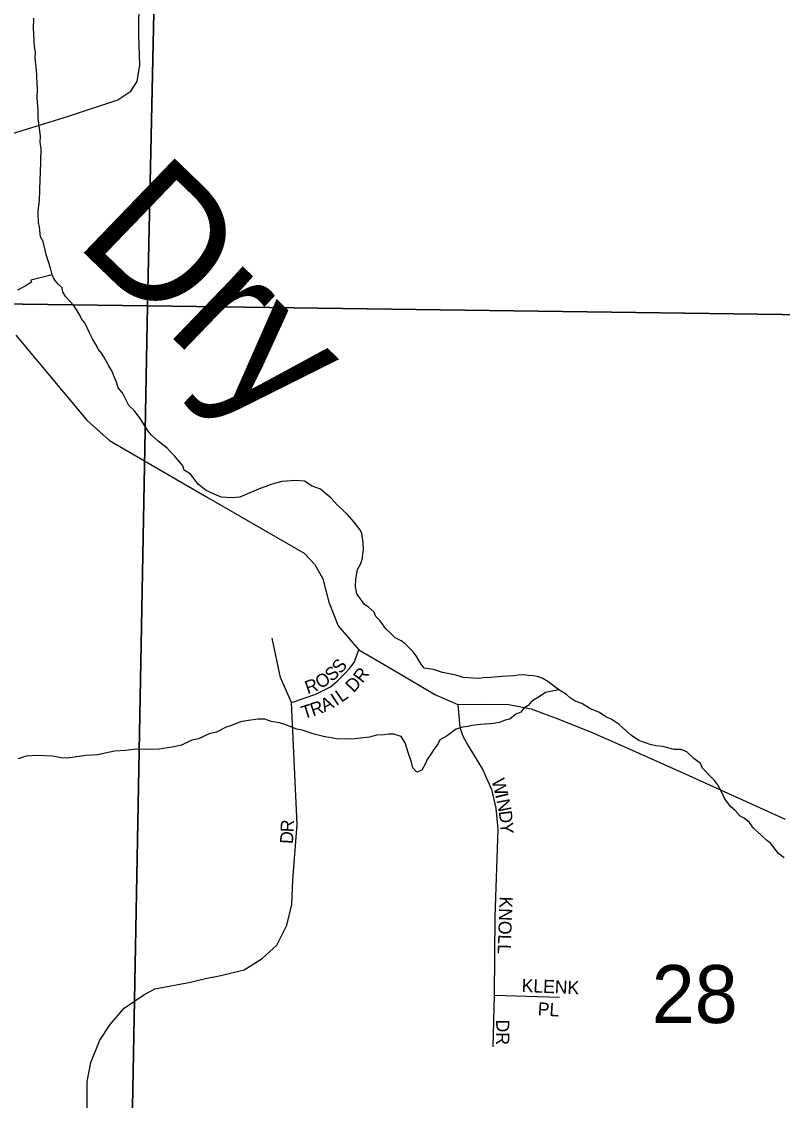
# Model space of a CAD drawing. Extents: x 0 to 34, y -2.3 to 22.
# Drawn here: x 4.226 to 4.776, y 15.821 to 16.601 of the extents above; entities that cross this region are included whole.
import ezdxf

# ---------------------------------------------------------------- set-up
doc = ezdxf.new("R2010")
doc.units = 0
for name, color, linetype in [('GM_X_County_Road', 7, 'Continuous'), ('GM_X_Minor_River', 7, 'Continuous'), ('GM_X_Minor_River_Text', 7, 'Continuous'), ('GM_X_Section', 7, 'Continuous'), ('GM_X_Section_Text', 7, 'Continuous'), ('GM_X_Township_Subdivision', 7, 'Continuous'), ('GM_X_Township_Subdivision_Text', 7, 'Continuous')]:
    doc.layers.add(name, color=color, linetype=linetype)

msp = doc.modelspace()

# ---------------------------------------------------------------- linework, layer by layer
at = {"layer": 'GM_X_County_Road'}
for p, q in [((4.31059, 16.60001), (4.31135, 16.62534)), ((4.31059, 16.59046), (4.31059, 16.60001)), ((4.31148, 16.56919), (4.31059, 16.59046)), ((4.30944, 16.55735), (4.31148, 16.56919)), ((4.30486, 16.55022), (4.30944, 16.55735)), ((4.29544, 16.54411), (4.30486, 16.55022)), ((4.25979, 16.53214), (4.29544, 16.54411)), ((4.17143, 16.50489), (4.25979, 16.53214)), ((4.22166, 16.37393), (4.27308, 16.31263)), ((4.27308, 16.31263), (4.28947, 16.29794)), ((4.28947, 16.29794), (4.35956, 16.25711)), ((4.35956, 16.25711), (4.43018, 16.21663)), ((4.43018, 16.21663), (4.43794, 16.2083)), ((4.43794, 16.2083), (4.44354, 16.19792)), ((4.44354, 16.19792), (4.44787, 16.18103)), ((4.44787, 16.18103), (4.45474, 16.16413)), ((4.45474, 16.16413), (4.46956, 16.14679)), ((4.46956, 16.14679), (4.48745, 16.13624)), ((4.48745, 16.13624), (4.50685, 16.12491)), ((4.50685, 16.12491), (4.52456, 16.11438)), ((4.52456, 16.11438), (4.54123, 16.1073)), ((4.54123, 16.1073), (4.56234, 16.10753)), ((4.56234, 16.10753), (4.57798, 16.10719)), ((4.57798, 16.10719), (4.59418, 16.10399)), ((4.59418, 16.10399), (4.61415, 16.09658)), ((4.61415, 16.09658), (4.63868, 16.08665)), ((4.63868, 16.08665), (4.65865, 16.07809)), ((4.65865, 16.07809), (4.70556, 16.05709)), ((4.70556, 16.05709), (4.77775, 16.02433))]:
    msp.add_line(p, q, dxfattribs=at)
at = {"layer": 'GM_X_Minor_River'}
for p, q in [((4.23456, 16.59498), (4.23479, 16.60295)), ((4.23486, 16.59231), (4.23456, 16.59498)), ((4.23507, 16.58623), (4.23486, 16.59231)), ((4.23535, 16.5828), (4.23507, 16.58623)), ((4.23597, 16.57822), (4.23535, 16.5828)), ((4.23586, 16.57442), (4.23597, 16.57822)), ((4.23674, 16.56528), (4.23586, 16.57442)), ((4.23702, 16.56185), (4.23674, 16.56528)), ((4.2372, 16.55501), (4.23702, 16.56185)), ((4.23749, 16.55196), (4.2372, 16.55501)), ((4.2373, 16.54551), (4.23749, 16.55196)), ((4.2378, 16.53638), (4.2373, 16.54551)), ((4.23801, 16.53067), (4.2378, 16.53638)), ((4.23862, 16.52534), (4.23801, 16.53067)), ((4.23954, 16.51771), (4.23862, 16.52534)), ((4.23941, 16.51354), (4.23954, 16.51771)), ((4.24003, 16.50858), (4.23941, 16.51354)), ((4.23952, 16.49112), (4.24003, 16.50858)), ((4.23895, 16.47139), (4.23939, 16.48657)), ((4.23939, 16.48657), (4.23952, 16.49112)), ((4.23797, 16.46382), (4.23895, 16.47139)), ((4.23789, 16.46116), (4.23797, 16.46382)), ((4.2381, 16.45546), (4.23789, 16.46116)), ((4.23876, 16.45202), (4.2381, 16.45546)), ((4.23971, 16.44515), (4.23876, 16.45202)), ((4.2415, 16.44168), (4.23971, 16.44515)), ((4.24218, 16.43862), (4.2415, 16.44168)), ((4.24386, 16.43135), (4.24218, 16.43862)), ((4.24598, 16.42559), (4.24386, 16.43135)), ((4.247, 16.42138), (4.24598, 16.42559)), ((4.24803, 16.41755), (4.23255, 16.41364)), ((4.24803, 16.41755), (4.247, 16.42138)), ((4.24946, 16.41447), (4.24803, 16.41755)), ((4.25201, 16.41098), (4.24946, 16.41447)), ((4.2284, 16.4094), (4.223, 16.40653)), ((4.23305, 16.4123), (4.2284, 16.4094)), ((4.23255, 16.41364), (4.23305, 16.4123)), ((4.25536, 16.40822), (4.25201, 16.41098)), ((4.25565, 16.40517), (4.25536, 16.40822)), ((4.25783, 16.40169), (4.25565, 16.40517)), ((4.26373, 16.39543), (4.25783, 16.40169)), ((4.26809, 16.38846), (4.26373, 16.39543)), ((4.26915, 16.38577), (4.26809, 16.38846)), ((4.27173, 16.38304), (4.26915, 16.38577)), ((4.27494, 16.37572), (4.27173, 16.38304)), ((4.27709, 16.37148), (4.27494, 16.37572)), ((4.27963, 16.36723), (4.27709, 16.37148)), ((4.28143, 16.36375), (4.27963, 16.36723)), ((4.28363, 16.36103), (4.28143, 16.36375)), ((4.28545, 16.35832), (4.28363, 16.36103)), ((4.28907, 16.35175), (4.28545, 16.35832)), ((4.29124, 16.34826), (4.28907, 16.35175)), ((4.29479, 16.33942), (4.29124, 16.34826)), ((4.29583, 16.33597), (4.29479, 16.33942)), ((4.29877, 16.33246), (4.29583, 16.33597)), ((4.30344, 16.32321), (4.29877, 16.33246)), ((4.30751, 16.31929), (4.30344, 16.32321)), ((4.31153, 16.31385), (4.30751, 16.31929)), ((4.31335, 16.31114), (4.31153, 16.31385)), ((4.31734, 16.30456), (4.31335, 16.31114)), ((4.31992, 16.30182), (4.31734, 16.30456)), ((4.32474, 16.2975), (4.31992, 16.30182)), ((4.33105, 16.29237), (4.32474, 16.2975)), ((4.334, 16.28925), (4.33105, 16.29237)), ((4.33658, 16.28651), (4.334, 16.28925)), ((4.34246, 16.2795), (4.33658, 16.28651)), ((4.34351, 16.27642), (4.34246, 16.2795)), ((4.34799, 16.27363), (4.34351, 16.27642)), ((4.35386, 16.26624), (4.34799, 16.27363)), ((4.35943, 16.26189), (4.35386, 16.26624)), ((4.40861, 16.26688), (4.40554, 16.26583)), ((4.41397, 16.26824), (4.40861, 16.26688)), ((4.42083, 16.2688), (4.41397, 16.26824)), ((4.42388, 16.26909), (4.42083, 16.2688)), ((4.43033, 16.26851), (4.42388, 16.26909)), ((4.43592, 16.26493), (4.43033, 16.26851)), ((4.36731, 16.25824), (4.35943, 16.26189)), ((4.37032, 16.25701), (4.36731, 16.25824)), ((4.39093, 16.26019), (4.38362, 16.25699)), ((4.39709, 16.26267), (4.39093, 16.26019)), ((4.40554, 16.26583), (4.39709, 16.26267)), ((4.44194, 16.26285), (4.43592, 16.26493)), ((4.44973, 16.25616), (4.44194, 16.26285)), ((4.3779, 16.2564), (4.37032, 16.25701)), ((4.38362, 16.25699), (4.3779, 16.2564)), ((4.45415, 16.25109), (4.44973, 16.25616)), ((4.46155, 16.24441), (4.45415, 16.25109)), ((4.46634, 16.23895), (4.46155, 16.24441)), ((4.47074, 16.2335), (4.46634, 16.23895)), ((4.4718, 16.2308), (4.47074, 16.2335)), ((4.47275, 16.22432), (4.4718, 16.2308)), ((4.47297, 16.21861), (4.47275, 16.22432)), ((4.47117, 16.20917), (4.47242, 16.21293)), ((4.47242, 16.21293), (4.47251, 16.21597)), ((4.47251, 16.21597), (4.47297, 16.21861)), ((4.46788, 16.20053), (4.46876, 16.20468)), ((4.46876, 16.20468), (4.47117, 16.20917)), ((4.46726, 16.19219), (4.46741, 16.19751)), ((4.46741, 16.19751), (4.46788, 16.20053)), ((4.46825, 16.18722), (4.46726, 16.19219)), ((4.47373, 16.17946), (4.46825, 16.18722)), ((4.47635, 16.17787), (4.47373, 16.17946)), ((4.48079, 16.17393), (4.47635, 16.17787)), ((4.48184, 16.17086), (4.48079, 16.17393)), ((4.48517, 16.16773), (4.48184, 16.17086)), ((4.48918, 16.16191), (4.48517, 16.16773)), ((4.49251, 16.15877), (4.48918, 16.16191)), ((4.49583, 16.15525), (4.49251, 16.15877)), ((4.50034, 16.15322), (4.49583, 16.15525)), ((4.50294, 16.15124), (4.50034, 16.15322)), ((4.50885, 16.14536), (4.50294, 16.15124)), ((4.51104, 16.14226), (4.50885, 16.14536)), ((4.51467, 16.13645), (4.51104, 16.14226)), ((4.51686, 16.13335), (4.51467, 16.13645)), ((4.52368, 16.13239), (4.51686, 16.13335)), ((4.53008, 16.13029), (4.52368, 16.13239)), ((4.53726, 16.12894), (4.53008, 16.13029)), ((4.54066, 16.12808), (4.53726, 16.12894)), ((4.54518, 16.1268), (4.54066, 16.12808)), ((4.55239, 16.12621), (4.54518, 16.1268)), ((4.55694, 16.12607), (4.55239, 16.12621)), ((4.55961, 16.12637), (4.55694, 16.12607)), ((4.56494, 16.12659), (4.55961, 16.12637)), ((4.57295, 16.12749), (4.56494, 16.12659)), ((4.57714, 16.12775), (4.57295, 16.12749)), ((4.58208, 16.12798), (4.57714, 16.12775)), ((4.58475, 16.12828), (4.58208, 16.12798)), ((4.58894, 16.12853), (4.58475, 16.12828)), ((4.59197, 16.12806), (4.58894, 16.12853)), ((4.59577, 16.12795), (4.59197, 16.12806)), ((4.5988, 16.12748), (4.59577, 16.12795)), ((4.60218, 16.12624), (4.5988, 16.12748)), ((4.60629, 16.12384), (4.60218, 16.12624)), ((4.6141, 16.11791), (4.60454, 16.11591)), ((4.61038, 16.12068), (4.60629, 16.12384)), ((4.6141, 16.11791), (4.61038, 16.12068)), ((4.61672, 16.11631), (4.6141, 16.11791)), ((4.60144, 16.11373), (4.59447, 16.10938)), ((4.60454, 16.11591), (4.60144, 16.11373)), ((4.6197, 16.11432), (4.61672, 16.11631)), ((4.62229, 16.11196), (4.6197, 16.11432)), ((4.62602, 16.10957), (4.62229, 16.11196)), ((4.58901, 16.1046), (4.58664, 16.10163)), ((4.5921, 16.10641), (4.58901, 16.1046)), ((4.59447, 16.10938), (4.5921, 16.10641)), ((4.63092, 16.10791), (4.62602, 16.10957)), ((4.63651, 16.10432), (4.63092, 16.10791)), ((4.64365, 16.10145), (4.63651, 16.10432)), ((4.38423, 16.09476), (4.37768, 16.09192)), ((4.38996, 16.09573), (4.38423, 16.09476)), ((4.39683, 16.09667), (4.38996, 16.09573)), ((4.40176, 16.09652), (4.39683, 16.09667)), ((4.40628, 16.09486), (4.40176, 16.09652)), ((4.41233, 16.09392), (4.40628, 16.09486)), ((4.57545, 16.09589), (4.57122, 16.09412)), ((4.57889, 16.09655), (4.57545, 16.09589)), ((4.58318, 16.10022), (4.57889, 16.09655)), ((4.58664, 16.10163), (4.58318, 16.10022)), ((4.64812, 16.09828), (4.64365, 16.10145)), ((4.65262, 16.09624), (4.64812, 16.09828)), ((4.65784, 16.09267), (4.65262, 16.09624)), ((4.36691, 16.08731), (4.36155, 16.08595)), ((4.37385, 16.0909), (4.36691, 16.08731)), ((4.37768, 16.09192), (4.37385, 16.0909)), ((4.4161, 16.09267), (4.41233, 16.09392)), ((4.42474, 16.08937), (4.4161, 16.09267)), ((4.42966, 16.08847), (4.42474, 16.08937)), ((4.4353, 16.0864), (4.42966, 16.08847)), ((4.53991, 16.08935), (4.53292, 16.08424)), ((4.54451, 16.09073), (4.53991, 16.08935)), ((4.54833, 16.09138), (4.54451, 16.09073)), ((4.55139, 16.09205), (4.54833, 16.09138)), ((4.55749, 16.09263), (4.55139, 16.09205)), ((4.5613, 16.09289), (4.55749, 16.09263)), ((4.56702, 16.09348), (4.5613, 16.09289)), ((4.57122, 16.09412), (4.56702, 16.09348)), ((4.66043, 16.09031), (4.65784, 16.09267)), ((4.66674, 16.0848), (4.66043, 16.09031)), ((4.34887, 16.08138), (4.34154, 16.0778)), ((4.35384, 16.08238), (4.34887, 16.08138)), ((4.36155, 16.08595), (4.35384, 16.08238)), ((4.43832, 16.08555), (4.4353, 16.0864)), ((4.44511, 16.08383), (4.43832, 16.08555)), ((4.44814, 16.08336), (4.44511, 16.08383)), ((4.45343, 16.08244), (4.44814, 16.08336)), ((4.46178, 16.08219), (4.45343, 16.08244)), ((4.46711, 16.08241), (4.46178, 16.08219)), ((4.47283, 16.083), (4.46711, 16.08241)), ((4.47741, 16.08362), (4.47283, 16.083)), ((4.48239, 16.08499), (4.47741, 16.08362)), ((4.4881, 16.0852), (4.48239, 16.08499)), ((4.49116, 16.08587), (4.4881, 16.0852)), ((4.49496, 16.08576), (4.49116, 16.08587)), ((4.50023, 16.08408), (4.49496, 16.08576)), ((4.50314, 16.07943), (4.50023, 16.08408)), ((4.50521, 16.07253), (4.50314, 16.07943)), ((4.52707, 16.0791), (4.5239, 16.07464)), ((4.52829, 16.08172), (4.52707, 16.0791)), ((4.53292, 16.08424), (4.52829, 16.08172)), ((4.67195, 16.08123), (4.66674, 16.0848)), ((4.68023, 16.07832), (4.67195, 16.08123)), ((4.29315, 16.07355), (4.28091, 16.07088)), ((4.30114, 16.07407), (4.29315, 16.07355)), ((4.30877, 16.07499), (4.30114, 16.07407)), ((4.31903, 16.07468), (4.30877, 16.07499)), ((4.32511, 16.07488), (4.31903, 16.07468)), ((4.33466, 16.07649), (4.32511, 16.07488)), ((4.34154, 16.0778), (4.33466, 16.07649)), ((4.50768, 16.06562), (4.50521, 16.07253)), ((4.5239, 16.07464), (4.52112, 16.07054)), ((4.68439, 16.07744), (4.68023, 16.07832)), ((4.68931, 16.07691), (4.68439, 16.07744)), ((4.69195, 16.07607), (4.68931, 16.07691)), ((4.69761, 16.07476), (4.69195, 16.07607)), ((4.70255, 16.07461), (4.69761, 16.07476)), ((4.70668, 16.07297), (4.70255, 16.07461)), ((4.71187, 16.06826), (4.70668, 16.07297)), ((4.22918, 16.06976), (4.22343, 16.06804)), ((4.23718, 16.07028), (4.22918, 16.06976)), ((4.24781, 16.06997), (4.23718, 16.07028)), ((4.25084, 16.0695), (4.24781, 16.06997)), ((4.25461, 16.06863), (4.25084, 16.0695)), ((4.25879, 16.0685), (4.25461, 16.06863)), ((4.26413, 16.0691), (4.25879, 16.0685)), ((4.27253, 16.07037), (4.26413, 16.0691)), ((4.28091, 16.07088), (4.27253, 16.07037)), ((4.50869, 16.06142), (4.50768, 16.06562)), ((4.51791, 16.06456), (4.51511, 16.0597)), ((4.51914, 16.06756), (4.51791, 16.06456)), ((4.52112, 16.07054), (4.51914, 16.06756)), ((4.71671, 16.06469), (4.71187, 16.06826)), ((4.71812, 16.06123), (4.71671, 16.06469)), ((4.51164, 16.05829), (4.50869, 16.06142)), ((4.51511, 16.0597), (4.51164, 16.05829)), ((4.72661, 16.05224), (4.71812, 16.06123)), ((4.72953, 16.04836), (4.72661, 16.05224)), ((4.73421, 16.0391), (4.72953, 16.04836)), ((4.73603, 16.03638), (4.73421, 16.0391)), ((4.7386, 16.03327), (4.73603, 16.03638)), ((4.74156, 16.03052), (4.7386, 16.03327)), ((4.74525, 16.02661), (4.74156, 16.03052)), ((4.74824, 16.025), (4.74525, 16.02661)), ((4.75195, 16.02185), (4.74824, 16.025)), ((4.75488, 16.01797), (4.75195, 16.02185)), ((4.76043, 16.01286), (4.75488, 16.01797)), ((4.7645, 16.00894), (4.76043, 16.01286)), ((4.7671, 16.00696), (4.7645, 16.00894)), ((4.77297, 15.99957), (4.7671, 16.00696)), ((4.77706, 15.99641), (4.77297, 15.99957))]:
    msp.add_line(p, q, dxfattribs=at)
at = {"layer": 'GM_X_Section'}
for p, q in [((4.33847, 17.37521), (4.31696, 16.39529)), ((4.31696, 16.39529), (4.33847, 17.37521)), ((4.31696, 16.39529), (3.51408, 16.40568)), ((3.51408, 16.40568), (4.31696, 16.39529)), ((4.31696, 16.39529), (4.29924, 15.44635)), ((4.29924, 15.44635), (4.31696, 16.39529)), ((5.31637, 16.38127), (4.31696, 16.39529)), ((4.31696, 16.39529), (5.31637, 16.38127))]:
    msp.add_line(p, q, dxfattribs=at)
at = {"layer": 'GM_X_Township_Subdivision'}
for p, q in [((4.41309, 16.12676), (4.40715, 16.15502)), ((4.46636, 16.13761), (4.46956, 16.14679)), ((4.46295, 16.13326), (4.46636, 16.13761)), ((4.42091, 16.10872), (4.41309, 16.12676)), ((4.45407, 16.12399), (4.45936, 16.12947)), ((4.45936, 16.12947), (4.46295, 16.13326)), ((4.4435, 16.11695), (4.44915, 16.12002)), ((4.44915, 16.12002), (4.45407, 16.12399)), ((4.42091, 16.10872), (4.43855, 16.11472)), ((4.43855, 16.11472), (4.4435, 16.11695)), ((4.42499, 16.0204), (4.42091, 16.10872)), ((4.54123, 16.1073), (4.54271, 16.09064)), ((4.54271, 16.09064), (4.54499, 16.08391)), ((4.54499, 16.08391), (4.54927, 16.07671)), ((4.54927, 16.07671), (4.55926, 16.05994)), ((4.55926, 16.05994), (4.56554, 16.04568)), ((4.56554, 16.04568), (4.56873, 16.03233)), ((4.56873, 16.03233), (4.57021, 16.01715)), ((4.42202, 15.98061), (4.42499, 16.0204)), ((4.57021, 16.01715), (4.56793, 15.95369)), ((4.42128, 15.96275), (4.42202, 15.98061)), ((4.41756, 15.94788), (4.42128, 15.96275)), ((4.41049, 15.93338), (4.41756, 15.94788)), ((4.56793, 15.95369), (4.56747, 15.89732)), ((4.39971, 15.9237), (4.41049, 15.93338)), ((4.3867, 15.91552), (4.39971, 15.9237)), ((4.36997, 15.91143), (4.3867, 15.91552)), ((4.3479, 15.90668), (4.35881, 15.9092)), ((4.35881, 15.9092), (4.36997, 15.91143)), ((4.31418, 15.89755), (4.32223, 15.90188)), ((4.32223, 15.90188), (4.3479, 15.90668)), ((4.29997, 15.88774), (4.31418, 15.89755)), ((4.56747, 15.89732), (4.56656, 15.85989)), ((4.56747, 15.89732), (4.61472, 15.89572)), ((4.28993, 15.87609), (4.29997, 15.88774)), ((4.2824, 15.86462), (4.28993, 15.87609)), ((4.2759, 15.84858), (4.2824, 15.86462)), ((4.2733, 15.83482), (4.2759, 15.84858)), ((4.2733, 15.81474), (4.2733, 15.83482))]:
    msp.add_line(p, q, dxfattribs=at)

# ---------------------------------------------------------------- texts
at = {"layer": 'GM_X_Minor_River_Text'}
msp.add_text('Dry', height=0.094695, rotation=316.05953, dxfattribs=at).set_placement((4.26336, 16.44074))
at = {"layer": 'GM_X_Section_Text'}
msp.add_text('28', height=0.041856, rotation=0.00001, dxfattribs=at).set_placement((4.68131, 15.87707))
at = {"layer": 'GM_X_Township_Subdivision_Text'}
for s, rotation, p in [('S', 38.97292, (4.44984, 16.12326)), ('S', 49.6101, (4.4564, 16.12879)), ('R', 52.56477, (4.47229, 16.12216)), ('R', 19.15108, (4.43262, 16.1146)), ('O', 32.50203, (4.44187, 16.1181)), ('D', 46.42544, (4.46583, 16.11528)), ('A', 26.75002, (4.44482, 16.10155)), ('I', 33.659, (4.45334, 16.10593)), ('L', 35.04499, (4.45702, 16.10838)), ('T', 17.39599, (4.4298, 16.09649)), ('R', 18.92974, (4.43643, 16.09857)), ('W', 283.9445, (4.56553, 16.05244)), ('I', 283.94459, (4.56814, 16.04193)), ('N', 281.05599, (4.56912, 16.03801)), ('D', 276.95693, (4.57069, 16.03001)), ('R', 87.52587, (4.42251, 16.01474)), ('Y', 273.63634, (4.57169, 16.02188)), ('D', 86.76924, (4.42203, 16.00628)), ('KNOLL', 267.99062, (4.57142, 15.96861)), ('KLENK', 357.56474, (4.58721, 15.89958)), ('PL', 356.42558, (4.59875, 15.8827)), ('DR', 270, (4.56892, 15.87951))]:
    msp.add_text(s, height=0.00947, rotation=rotation, dxfattribs=at).set_placement(p)

doc.saveas('drawing.dxf')
